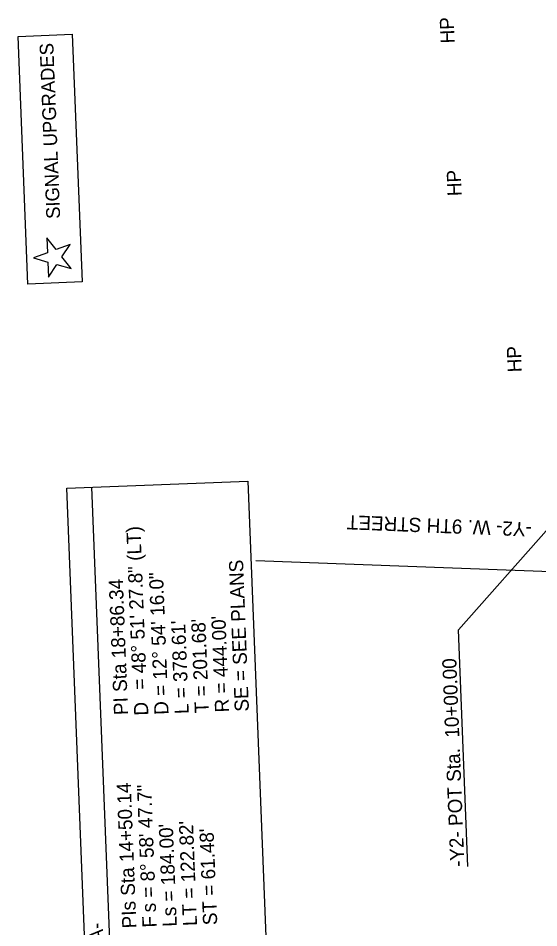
# Model space of a CAD drawing. Extents: x 1627861 to 1629601, y 761281 to 766239.
# Drawn here: x 1627958.1 to 1628215.6, y 761933.4 to 762383.2 of the extents above; entities that cross this region are included whole.
import ezdxf

# ---------------------------------------------------------------- set-up
doc = ezdxf.new("R2010")
doc.units = 0
for name, color, linetype in [('Exist Other Culture Sign Leader', 7, 'Continuous'), ('Exist Right of Way Line Leader', 7, 'Continuous'), ('Exist Utilities Gas UG Line Text', 7, 'Continuous'), ('Exist Utilities Power UG Cable SUE LOS B Cogo Elevation', 7, 'Continuous'), ('Exist Utilities Water Fire Hydrant Cogo Number', 7, 'Continuous'), ('Old_Level_2', 7, 'Continuous')]:
    doc.layers.add(name, color=color, linetype=linetype)

msp = doc.modelspace()

# ---------------------------------------------------------------- linework, layer by layer
at = {"layer": 'Exist Right of Way Line Leader'}
for p in [(1628220.51, 762131.12), (1628180.54, 761963.66)]:
    msp.add_line(p, (1628175.92, 762080.71), dxfattribs=at)
at = {"layer": 'Exist Utilities Gas UG Line Text'}
msp.add_line((1628011.94, 761709.08), (1627994.5, 762151.23), dxfattribs=at)
msp.add_lwpolyline([(1627999.6, 761708.6), (1627982.17, 762150.75), (1628071.71, 762154.28), (1628089.14, 761712.13)], close=True, dxfattribs=at)
at = {"layer": 'Exist Utilities Power UG Cable SUE LOS B Cogo Elevation'}
msp.add_lwpolyline([(1627972.71, 762262.58), (1627973.01, 762255.18), (1627977.12, 762261.34), (1627984.26, 762259.32), (1627979.67, 762265.15), (1627983.78, 762271.32), (1627976.83, 762268.75), (1627972.24, 762274.57), (1627972.53, 762267.16), (1627965.57, 762264.59), (1627972.71, 762262.58)], dxfattribs=at)
at = {"layer": 'Exist Utilities Water Fire Hydrant Cogo Number'}
msp.add_line((1628075.65, 762115.08), (1628420.61, 762102.01), dxfattribs=at)
at = {"layer": 'Old_Level_2'}
msp.add_lwpolyline([(1627962.89, 762251.7), (1627958.06, 762374.19), (1627984.82, 762375.24), (1627989.65, 762252.76)], close=True, dxfattribs=at)

# ---------------------------------------------------------------- texts
at = {"layer": 'Exist Other Culture Sign Leader'}
for s, height, rotation, p in [('HP', 7, 92.2582, (1628174.03, 762370.82)), ('SIGNAL UPGRADES', 6.8072, 92.2582, (1627978.85, 762284.06)), ('HP', 7, 92.2582, (1628177.48, 762295.29)), ('HP', 7, 92.2582, (1628207.24, 762208.2)), ('-Y2- W. 9TH STREET', 7, 177.7354, (1628212.25, 762133.82))]:
    msp.add_text(s, height=height, rotation=rotation, dxfattribs=at).set_placement(p)
at = {"layer": 'Exist Right of Way Line Leader'}
msp.add_text('-Y2- POT Sta.  10+00.00', height=7, rotation=92.2582, dxfattribs=at).set_placement((1628178.84, 761963.59))
at = {"layer": 'Exist Utilities Gas UG Line Text'}
for s, p in [('= 48%%d 51\' 27.8" (LT)', (1628021.69, 762051.26)), ('SE = SEE PLANS', (1628072.24, 762040.4)), ('D = 12%%d 54\' 16.0"', (1628032.48, 762038.83)), ('PI Sta 18+86.34', (1628012.47, 762038.71)), ("R = 444.00'", (1628062.46, 762040.01)), ("L = 378.61'", (1628042.47, 762039.22)), ("T = 201.68'", (1628052.46, 762039.62)), ('D', (1628022.49, 762038.44)), ('PIs Sta 14+50.14', (1628016.59, 761933.24)), ('s = 8%%d 58\' 47.7"', (1628026.29, 761941.14)), ("Ls = 184.00'", (1628036.57, 761934.02)), ("LT = 122.82'", (1628046.57, 761934.42)), ("ST = 61.48'", (1628056.56, 761934.81)), ('F', (1628026.58, 761933.63)), ('-RPA-', (1628000.95, 761910.56))]:
    msp.add_text(s, height=7, rotation=92.2582, dxfattribs=at).set_placement(p)

doc.saveas('drawing.dxf')
